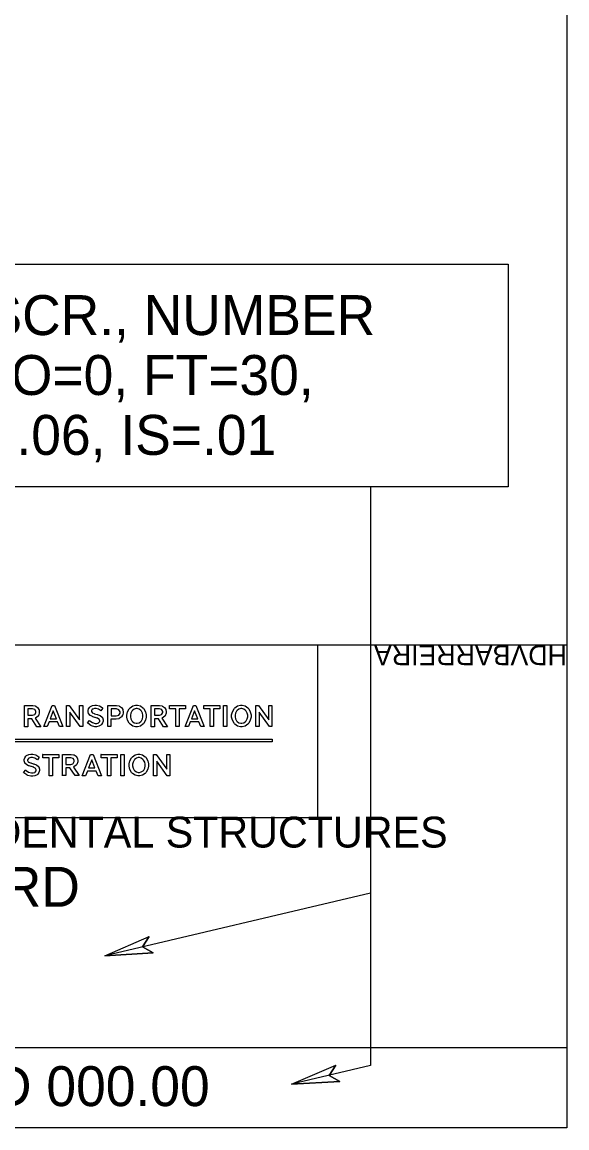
# Model space of a CAD drawing. Extents: x 0 to 1549163, y -476626 to 622136.
# Drawn here: x 6.132 to 7.768, y 5.937 to 9.261 of the extents above; entities that cross this region are included whole.
import ezdxf

# ---------------------------------------------------------------- set-up
doc = ezdxf.new("R2010")
doc.units = 0
for name, color, linetype in [('BORD-LINE', 7, 'Continuous'), ('DETL-DIMS', 7, 'Continuous'), ('DETL-NOTE', 7, 'Continuous'), ('MSHA-LOGO', 7, 'Continuous'), ('TTLB-TEXT', 7, 'Continuous'), ('USER-BORD', 7, 'Continuous'), ('USER-LINE', 7, 'Continuous')]:
    doc.layers.add(name, color=color, linetype=linetype)

msp = doc.modelspace()

# ---------------------------------------------------------------- linework, layer by layer
at = {"layer": 'BORD-LINE'}
msp.add_line((7.7685, 7.3883), (0.3943, 7.3883), dxfattribs=at)
at = {"layer": 'DETL-DIMS'}
for p, q in [((7.1787, 7.8648), (7.1787, 6.1246)), ((7.1787, 6.6431), (6.3803, 6.4551)), ((6.3803, 6.4551), (6.5137, 6.5124)), ((6.4932, 6.4817), (6.5137, 6.5124)), ((6.5253, 6.4633), (6.4932, 6.4817)), ((6.3803, 6.4551), (6.5253, 6.4633)), ((6.9411, 6.0687), (7.0745, 6.126)), ((7.1787, 6.1246), (6.9411, 6.0687)), ((7.054, 6.0953), (7.0745, 6.126)), ((7.0861, 6.0769), (7.054, 6.0953)), ((6.9411, 6.0687), (7.0861, 6.0769))]:
    msp.add_line(p, q, dxfattribs=at)
for points in [[(6.5253, 6.4633), (6.3803, 6.4551), (6.5137, 6.5124), (6.4932, 6.4817)], [(7.0861, 6.0769), (6.9411, 6.0687), (7.0745, 6.126), (7.054, 6.0953)]]:
    msp.add_lwpolyline(points, close=True, dxfattribs=at)
at = {"layer": 'MSHA-LOGO'}
for points in [[(6.1386, 7.1437), (6.1386, 7.2072), (6.1608, 7.2072), (6.1636, 7.2072), (6.1711, 7.2058), (6.1719, 7.2055), (6.1727, 7.2053), (6.1784, 7.2014), (6.1788, 7.2009), (6.1792, 7.2005), (6.1822, 7.1953), (6.1824, 7.1947), (6.1827, 7.1941), (6.1834, 7.1889), (6.1834, 7.1871), (6.1834, 7.1842), (6.1807, 7.1764), (6.1801, 7.1756), (6.1795, 7.1748), (6.1719, 7.169), (6.171, 7.1687), (6.188, 7.1434), (6.1759, 7.1434), (6.1605, 7.1667), (6.1484, 7.1667), (6.1484, 7.1434), (6.1386, 7.1434)], [(6.1484, 7.197), (6.1484, 7.1776), (6.1612, 7.1776), (6.1633, 7.1776), (6.1694, 7.1798), (6.17, 7.1802), (6.1705, 7.1806), (6.1733, 7.186), (6.1733, 7.1878), (6.1733, 7.1895), (6.1708, 7.1943), (6.1703, 7.1947), (6.1698, 7.1951), (6.1631, 7.197), (6.1608, 7.197)], [(6.2217, 7.2075), (6.2292, 7.2075), (6.2541, 7.144), (6.2436, 7.144), (6.2381, 7.1582), (6.2125, 7.1582), (6.207, 7.144), (6.1968, 7.144)], [(6.2161, 7.1674), (6.2348, 7.1674), (6.2253, 7.1914)], [(6.3064, 7.1437), (6.275, 7.1871), (6.275, 7.1437), (6.2655, 7.1437), (6.2655, 7.2072), (6.2731, 7.2072), (6.3045, 7.1638), (6.3045, 7.2072), (6.314, 7.2072), (6.314, 7.1437)], [(6.3627, 7.1661), (6.3624, 7.1664), (6.3583, 7.1691), (6.3578, 7.1694), (6.3573, 7.1695), (6.3516, 7.1712), (6.351, 7.1713), (6.3503, 7.1715), (6.3441, 7.1734), (6.3434, 7.1736), (6.3428, 7.1739), (6.337, 7.1766), (6.3366, 7.1769), (6.3361, 7.1773), (6.332, 7.1816), (6.3316, 7.1822), (6.3313, 7.1828), (6.3297, 7.1885), (6.3297, 7.1904), (6.3297, 7.1921), (6.3312, 7.1973), (6.3348, 7.2023), (6.3359, 7.2032), (6.3369, 7.2041), (6.343, 7.2072), (6.3497, 7.2085), (6.3519, 7.2085), (6.3551, 7.2085), (6.3645, 7.2062), (6.3726, 7.2009), (6.3739, 7.1993), (6.3686, 7.1914), (6.3674, 7.1925), (6.3607, 7.1963), (6.3539, 7.198), (6.3516, 7.198), (6.3495, 7.198), (6.3437, 7.1963), (6.3431, 7.196), (6.3425, 7.1957), (6.3398, 7.1917), (6.3398, 7.1904), (6.3398, 7.1892), (6.342, 7.1858), (6.3424, 7.1855), (6.3428, 7.1852), (6.3483, 7.1827), (6.349, 7.1825), (6.3496, 7.1824), (6.3568, 7.1805), (6.3575, 7.1802), (6.3582, 7.18), (6.3653, 7.1773), (6.366, 7.1769), (6.3667, 7.1766), (6.3721, 7.172), (6.3726, 7.1713), (6.373, 7.1707), (6.3752, 7.1642), (6.3752, 7.1621), (6.3752, 7.1602), (6.3736, 7.1546), (6.37, 7.1495), (6.369, 7.1486), (6.3679, 7.1477), (6.3619, 7.1446), (6.3556, 7.1434), (6.3536, 7.1434), (6.3499, 7.1434), (6.3403, 7.1461), (6.3392, 7.1467), (6.338, 7.1472), (6.329, 7.1541), (6.3284, 7.1549), (6.3343, 7.1624), (6.3356, 7.161), (6.3431, 7.1556), (6.3515, 7.1532), (6.3542, 7.1532), (6.3562, 7.1532), (6.3617, 7.1549), (6.3621, 7.1552), (6.3626, 7.1555), (6.365, 7.1595), (6.365, 7.1608), (6.3649, 7.1614), (6.3631, 7.1657)], [(6.3889, 7.1437), (6.3889, 7.2072), (6.4118, 7.2072), (6.4148, 7.2072), (6.4228, 7.2058), (6.4236, 7.2055), (6.4244, 7.2052), (6.4304, 7.2011), (6.4308, 7.2006), (6.4312, 7.2001), (6.4342, 7.1946), (6.4344, 7.194), (6.4346, 7.1935), (6.4354, 7.1882), (6.4354, 7.1865), (6.4354, 7.1846), (6.4343, 7.1795), (6.4341, 7.1789), (6.4338, 7.1783), (6.4306, 7.1728), (6.4301, 7.1723), (6.4297, 7.1718), (6.4234, 7.1677), (6.4226, 7.1674), (6.4218, 7.1671), (6.4141, 7.1657), (6.4115, 7.1657), (6.3984, 7.1657), (6.3984, 7.144), (6.3889, 7.144)], [(6.3991, 7.197), (6.3991, 7.1756), (6.4121, 7.1756), (6.4147, 7.1756), (6.4224, 7.1783), (6.4259, 7.1844), (6.4259, 7.1865), (6.4259, 7.1884), (6.4226, 7.1943), (6.4152, 7.197), (6.4128, 7.197)], [(6.455, 7.1986), (6.4564, 7.2002), (6.4643, 7.2057), (6.4728, 7.2082), (6.4756, 7.2082), (6.4784, 7.2082), (6.4869, 7.2059), (6.4948, 7.2005), (6.4962, 7.199), (6.4976, 7.1974), (6.5026, 7.1885), (6.5048, 7.1788), (6.5048, 7.1756), (6.5048, 7.1724), (6.5026, 7.1628), (6.4976, 7.1538), (6.4962, 7.1522), (6.4948, 7.1507), (6.4869, 7.1453), (6.4784, 7.143), (6.4756, 7.143), (6.4728, 7.143), (6.4643, 7.1453), (6.4564, 7.1507), (6.455, 7.1522), (6.4536, 7.1538), (6.4487, 7.1627), (6.4465, 7.1724), (6.4465, 7.1756), (6.4466, 7.1779), (6.4488, 7.1882), (6.4536, 7.1971)], [(6.4625, 7.1598), (6.4634, 7.1587), (6.4686, 7.1551), (6.4741, 7.1536), (6.476, 7.1536), (6.4778, 7.1536), (6.4833, 7.1551), (6.4885, 7.1587), (6.4894, 7.1598), (6.4903, 7.1608), (6.4935, 7.1667), (6.4949, 7.1734), (6.4949, 7.1756), (6.4949, 7.1778), (6.4935, 7.1845), (6.4903, 7.1904), (6.4894, 7.1914), (6.4885, 7.1925), (6.4833, 7.1961), (6.4778, 7.1976), (6.476, 7.1976), (6.4742, 7.1976), (6.4688, 7.1961), (6.4635, 7.1925), (6.4625, 7.1914), (6.4616, 7.1904), (6.4584, 7.1845), (6.457, 7.1778), (6.457, 7.1756), (6.457, 7.1734), (6.4583, 7.1667), (6.4616, 7.1608)], [(6.5195, 7.1437), (6.5195, 7.2072), (6.5417, 7.2072), (6.5445, 7.2072), (6.552, 7.2058), (6.5529, 7.2055), (6.5536, 7.2053), (6.5593, 7.2014), (6.5597, 7.2009), (6.5601, 7.2005), (6.5631, 7.1953), (6.5633, 7.1947), (6.5635, 7.1941), (6.5643, 7.1889), (6.5643, 7.1871), (6.5643, 7.1842), (6.5616, 7.1764), (6.561, 7.1756), (6.5605, 7.1748), (6.5528, 7.169), (6.5519, 7.1687), (6.5689, 7.1434), (6.5568, 7.1434), (6.5414, 7.1667), (6.5293, 7.1667), (6.5293, 7.1434), (6.5195, 7.1434)], [(6.5293, 7.197), (6.5293, 7.1776), (6.5421, 7.1776), (6.5443, 7.1776), (6.5503, 7.1798), (6.5509, 7.1802), (6.5514, 7.1806), (6.5542, 7.186), (6.5542, 7.1878), (6.5542, 7.1895), (6.5517, 7.1943), (6.5512, 7.1947), (6.5507, 7.1951), (6.544, 7.197), (6.5417, 7.197)], [(6.5745, 7.2075), (6.6226, 7.2075), (6.6226, 7.1973), (6.6036, 7.1973), (6.6036, 7.144), (6.5938, 7.144), (6.5938, 7.1973), (6.5748, 7.1973), (6.5748, 7.2075)], [(6.6465, 7.2075), (6.654, 7.2075), (6.6789, 7.144), (6.6684, 7.144), (6.6628, 7.1582), (6.637, 7.1582), (6.6314, 7.144), (6.6216, 7.144)], [(6.6406, 7.1674), (6.6592, 7.1674), (6.6497, 7.1914)], [(6.6775, 7.2075), (6.7257, 7.2075), (6.7257, 7.1973), (6.7067, 7.1973), (6.7067, 7.144), (6.6969, 7.144), (6.6969, 7.1973), (6.6779, 7.1973), (6.6779, 7.2075)], [(6.7371, 7.2075), (6.7469, 7.2075), (6.7469, 7.144), (6.7371, 7.144)], [(6.7698, 7.1986), (6.7712, 7.2002), (6.7791, 7.2057), (6.7876, 7.2082), (6.7904, 7.2082), (6.7933, 7.2082), (6.8017, 7.2059), (6.8097, 7.2005), (6.8111, 7.199), (6.8124, 7.1974), (6.8174, 7.1885), (6.8196, 7.1788), (6.8196, 7.1756), (6.8196, 7.1724), (6.8174, 7.1628), (6.8124, 7.1538), (6.8111, 7.1522), (6.8097, 7.1507), (6.8017, 7.1453), (6.7933, 7.143), (6.7904, 7.143), (6.7876, 7.143), (6.7791, 7.1453), (6.7712, 7.1507), (6.7698, 7.1522), (6.7684, 7.1538), (6.7635, 7.1627), (6.7613, 7.1724), (6.7613, 7.1756), (6.7613, 7.1788), (6.7634, 7.1882), (6.7684, 7.1971)], [(6.777, 7.1598), (6.7779, 7.1587), (6.7831, 7.1551), (6.7886, 7.1536), (6.7904, 7.1536), (6.7923, 7.1536), (6.7978, 7.1551), (6.803, 7.1587), (6.8039, 7.1598), (6.8048, 7.1608), (6.808, 7.1667), (6.8094, 7.1734), (6.8094, 7.1756), (6.8094, 7.1778), (6.808, 7.1845), (6.8048, 7.1904), (6.8039, 7.1914), (6.803, 7.1925), (6.7978, 7.1961), (6.7923, 7.1976), (6.7904, 7.1976), (6.7886, 7.1976), (6.7832, 7.1961), (6.778, 7.1925), (6.777, 7.1914), (6.7761, 7.1904), (6.7729, 7.1845), (6.7715, 7.1778), (6.7715, 7.1756), (6.7715, 7.1734), (6.7729, 7.1667), (6.7761, 7.1608)], [(6.8749, 7.1437), (6.8435, 7.1871), (6.8435, 7.1437), (6.834, 7.1437), (6.834, 7.2072), (6.8415, 7.2072), (6.8729, 7.1638), (6.8729, 7.2072), (6.8824, 7.2072), (6.8824, 7.1437)], [(4.7668, 7.1057), (6.8835, 7.1057), (6.8835, 7.0979), (4.7668, 7.0979)], [(6.1718, 7.0181), (6.1714, 7.0185), (6.1672, 7.0211), (6.1667, 7.0214), (6.1661, 7.0215), (6.1603, 7.0235), (6.1596, 7.0236), (6.159, 7.0238), (6.1526, 7.0256), (6.152, 7.0258), (6.1513, 7.0261), (6.1455, 7.0287), (6.1449, 7.0291), (6.1444, 7.0294), (6.1401, 7.034), (6.1398, 7.0345), (6.1395, 7.0351), (6.1379, 7.0409), (6.1379, 7.0429), (6.1379, 7.0446), (6.1395, 7.0499), (6.1433, 7.0548), (6.1443, 7.0557), (6.1453, 7.0566), (6.1515, 7.0596), (6.1583, 7.0609), (6.1606, 7.0609), (6.1638, 7.0609), (6.1733, 7.0585), (6.1816, 7.0531), (6.183, 7.0515), (6.1775, 7.0435), (6.1763, 7.0446), (6.1696, 7.0486), (6.1626, 7.0503), (6.1603, 7.0503), (6.1581, 7.0503), (6.1522, 7.0487), (6.1516, 7.0483), (6.1511, 7.048), (6.1481, 7.0439), (6.1481, 7.0425), (6.1481, 7.0413), (6.1503, 7.0378), (6.1507, 7.0374), (6.1511, 7.0371), (6.1567, 7.0347), (6.1574, 7.0345), (6.1581, 7.0344), (6.1652, 7.0322), (6.166, 7.032), (6.1668, 7.0317), (6.174, 7.029), (6.1747, 7.0287), (6.1753, 7.0284), (6.1809, 7.0236), (6.1814, 7.023), (6.1818, 7.0223), (6.1839, 7.0158), (6.1839, 7.0136), (6.1839, 7.0118), (6.1823, 7.006), (6.1786, 7.0007), (6.1775, 6.9998), (6.1765, 6.999), (6.1704, 6.9958), (6.164, 6.9944), (6.1619, 6.9944), (6.1582, 6.9944), (6.1484, 6.997), (6.1472, 6.9976), (6.146, 6.9982), (6.1369, 7.0051), (6.1363, 7.0059), (6.1424, 7.0136), (6.1436, 7.0121), (6.1513, 7.0067), (6.1599, 7.0043), (6.1628, 7.0043), (6.1648, 7.0043), (6.1703, 7.0059), (6.1708, 7.0063), (6.1713, 7.0066), (6.1737, 7.0107), (6.1737, 7.012), (6.1737, 7.0136), (6.1721, 7.0178)], [(6.1932, 7.0602), (6.2418, 7.0602), (6.2418, 7.0496), (6.2226, 7.0496), (6.2226, 6.996), (6.2127, 6.996), (6.2127, 7.0496), (6.1935, 7.0496), (6.1935, 7.0602)], [(6.2533, 6.996), (6.2533, 7.0602), (6.2759, 7.0602), (6.2787, 7.0602), (6.2863, 7.0588), (6.2871, 7.0586), (6.2879, 7.0584), (6.2938, 7.0546), (6.2942, 7.0541), (6.2946, 7.0536), (6.2975, 7.0483), (6.2977, 7.0477), (6.2978, 7.0471), (6.2986, 7.042), (6.2986, 7.0403), (6.2986, 7.0374), (6.2956, 7.0295), (6.2951, 7.0287), (6.2945, 7.0279), (6.2868, 7.0223), (6.2858, 7.022), (6.3031, 6.9963), (6.291, 6.9963), (6.2753, 7.0197), (6.2631, 7.0197), (6.2631, 6.9963), (6.2533, 6.9963)], [(6.2631, 7.0496), (6.2631, 7.03), (6.2759, 7.03), (6.2782, 7.03), (6.2843, 7.0322), (6.2849, 7.0326), (6.2854, 7.0331), (6.2881, 7.0383), (6.2881, 7.04), (6.2881, 7.0418), (6.2857, 7.0466), (6.2852, 7.047), (6.2847, 7.0474), (6.2779, 7.0496), (6.2756, 7.0496)], [(6.3373, 7.0602), (6.3449, 7.0602), (6.3702, 6.996), (6.3597, 6.996), (6.3539, 7.0101), (6.3277, 7.0101), (6.3223, 6.996), (6.312, 6.996)], [(6.3686, 7.0602), (6.4172, 7.0602), (6.4172, 7.0496), (6.398, 7.0496), (6.398, 6.996), (6.3881, 6.996), (6.3881, 7.0496), (6.3689, 7.0496), (6.3689, 7.0602)], [(6.4287, 7.0602), (6.4386, 7.0602), (6.4386, 6.996), (6.4287, 6.996)], [(6.4616, 7.0512), (6.463, 7.0528), (6.4711, 7.0584), (6.4795, 7.0609), (6.4823, 7.0609), (6.4852, 7.0609), (6.4937, 7.0585), (6.5017, 7.0531), (6.5031, 7.0515), (6.5044, 7.05), (6.5095, 7.041), (6.5117, 7.0313), (6.5117, 7.0281), (6.5117, 7.0249), (6.5096, 7.0153), (6.5045, 7.0063), (6.5031, 7.0047), (6.5017, 7.0031), (6.4935, 6.9976), (6.4851, 6.9953), (6.4823, 6.9953), (6.4795, 6.9953), (6.4709, 6.9977), (6.4629, 7.0031), (6.4616, 7.0047), (6.4601, 7.0062), (6.4551, 7.0152), (6.4529, 7.0249), (6.4529, 7.0281), (6.4529, 7.0313), (6.4551, 7.0408), (6.4601, 7.0497)], [(6.4689, 7.012), (6.4699, 7.011), (6.4751, 7.0074), (6.4805, 7.0059), (6.4823, 7.0059), (6.4842, 7.0059), (6.4898, 7.0074), (6.4951, 7.011), (6.4961, 7.012), (6.497, 7.0131), (6.5002, 7.0191), (6.5015, 7.0258), (6.5015, 7.0281), (6.5015, 7.0303), (6.5001, 7.037), (6.4967, 7.0431), (6.4958, 7.0441), (6.4948, 7.0452), (6.4895, 7.0488), (6.4841, 7.0503), (6.4823, 7.0503), (6.4805, 7.0503), (6.475, 7.0488), (6.4698, 7.0452), (6.4689, 7.0441), (6.468, 7.0431), (6.4649, 7.0371), (6.4635, 7.0303), (6.4635, 7.0281), (6.4635, 7.0258), (6.4649, 7.0191), (6.468, 7.0131)], [(6.568, 6.996), (6.5363, 7.0397), (6.5363, 6.996), (6.5267, 6.996), (6.5267, 7.0602), (6.5344, 7.0602), (6.5661, 7.0162), (6.5661, 7.0602), (6.5756, 7.0602), (6.5756, 6.996)], [(6.3315, 7.0197), (6.3504, 7.0197), (6.3408, 7.0441)]]:
    msp.add_lwpolyline(points, close=True, dxfattribs=at)
at = {"layer": 'TTLB-TEXT'}
msp.add_line((7.7685, 7.3883), (0.3943, 7.3883), dxfattribs=at)
for points in [[(0.3943, 16.2906), (7.7685, 16.2906), (7.7685, 5.9375), (0.3943, 5.9375)], [(4.8334, 8.534), (7.5921, 8.534), (7.5921, 7.8648), (4.8334, 7.8648)]]:
    msp.add_lwpolyline(points, close=True, dxfattribs=at)
at = {"layer": 'USER-BORD'}
for p, q in [((7.7685, 7.3883), (0.3943, 7.3883)), ((3.2956, 6.1793), (7.7685, 6.1793)), ((6.4001, 6.0629), (6.4001, 6.0629))]:
    msp.add_line(p, q, dxfattribs=at)
at = {"layer": 'USER-LINE'}
msp.add_lwpolyline([(7.0197, 6.8692), (4.0486, 6.8692), (4.0486, 7.3899), (7.0197, 7.3899)], close=True, dxfattribs=at)

# ---------------------------------------------------------------- texts
at = {"layer": 'DETL-NOTE'}
msp.add_text('STANDARDS FOR HIGHWAYS AND INCIDENTAL STRUCTURES', height=0.09269, dxfattribs=at).set_placement((3.6914, 6.7803))
at = {"layer": 'TTLB-TEXT'}
for s, height, p in [('STANDARD DESCR., NUMBER  ', 0.12, (4.8745, 8.3205)), ('LV=13, WT=0, CO=0, FT=30, ', 0.12, (4.9028, 8.1405)), ('TX=.12 , LS=.06, IS=.01', 0.12, (5.169, 7.9605)), ('STANDARDS FOR HIGHWAYS AND INCIDENTAL STRUCTURES', 0.09269, (3.6913, 6.7802)), ('SAMPLE STANDARD', 0.12, (4.727, 6.6021)), ('MD 000.00', 0.12, (5.9104, 6.0029))]:
    msp.add_text(s, height=height, dxfattribs=at).set_placement(p)
at = {"layer": 'USER-BORD'}
msp.add_text('HDVBARREIRA', height=0.06, rotation=180, dxfattribs=at).set_placement((7.7685, 7.3883))

doc.saveas('drawing.dxf')
